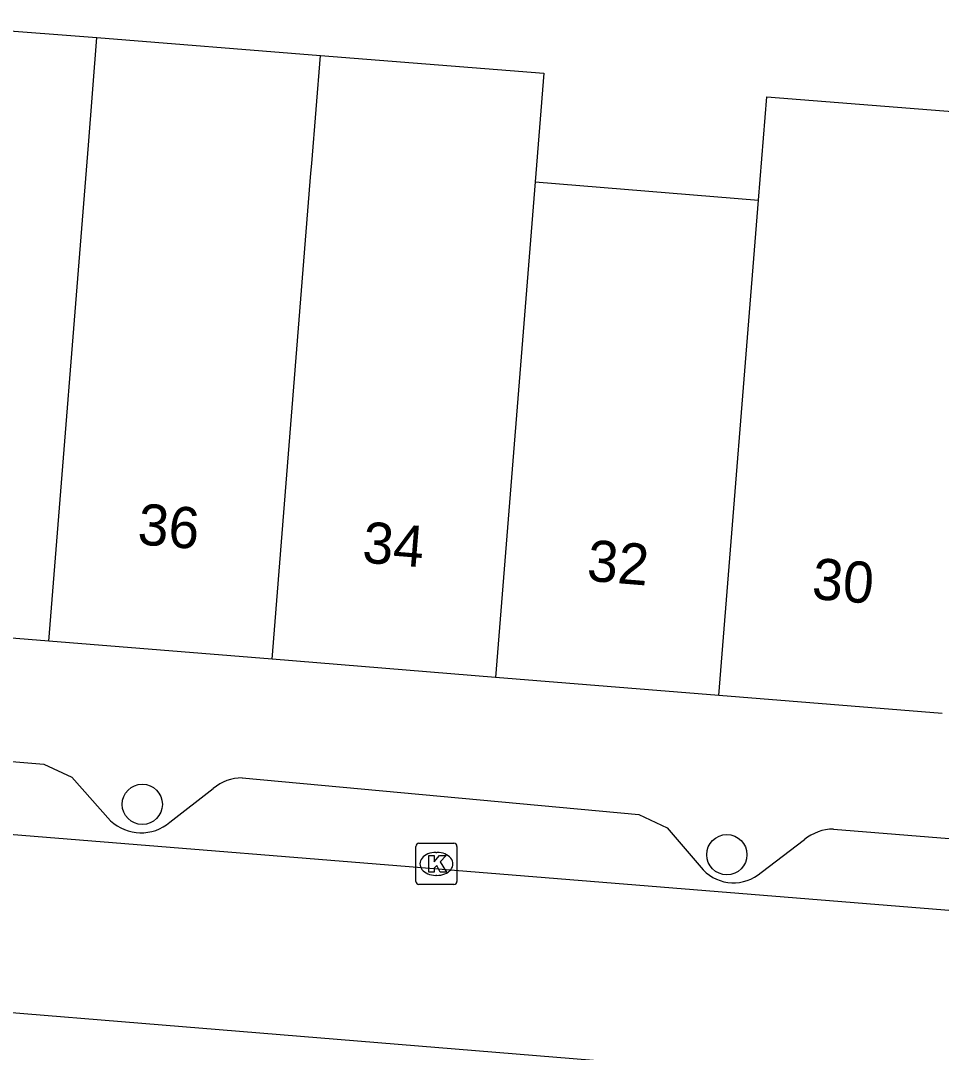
# Model space of a CAD drawing. Extents: x 159961 to 160856, y 382704 to 383353.
# Drawn here: x 160473.36 to 160495.73, y 383140.41 to 383165.49 of the extents above; entities that cross this region are included whole.
import ezdxf

# ---------------------------------------------------------------- set-up
doc = ezdxf.new("R2010")
doc.units = 0
for name, color, linetype in [('IMGEO_Boom', 7, 'Continuous'), ('IMGEO_Kolk', 7, 'Continuous'), ('IMGEO_Pand', 7, 'Continuous'), ('IMGEO_Pand_nummerreeks', 7, 'Continuous'), ('IMGEO_Rijbaan_lokaal_open', 7, 'Continuous'), ('IMGEO_Voetpad_open', 7, 'Continuous')]:
    doc.layers.add(name, color=color, linetype=linetype)

msp = doc.modelspace()

# ---------------------------------------------------------------- linework, layer by layer
at = {"layer": 'IMGEO_Boom'}
for centre in [(160476.316, 383146.443), (160490.517, 383145.219)]:
    msp.add_circle(centre, 0.489, dxfattribs=at)
at = {"layer": 'IMGEO_Kolk'}
for p, q in [((160483.035, 383145.496), (160483.887, 383145.496)), ((160482.96, 383144.57), (160482.96, 383145.422)), ((160483.448, 383145.276), (160483.473, 383145.276)), ((160483.961, 383145.422), (160483.961, 383144.57)), ((160483.471, 383144.716), (160483.446, 383144.716)), ((160483.887, 383144.496), (160483.035, 383144.496))]:
    msp.add_line(p, q, dxfattribs=at)
for points in [[(160483.035, 383145.496), (160483.887, 383145.496)], [(160482.96, 383144.57), (160482.96, 383145.422)], [(160483.961, 383145.422), (160483.961, 383144.57)], [(160483.281, 383145.196), (160483.404, 383145.196), (160483.404, 383145.045), (160483.534, 383145.196), (160483.698, 383145.196), (160483.552, 383145.045), (160483.705, 383144.796), (160483.553, 383144.796), (160483.468, 383144.96), (160483.404, 383144.893), (160483.404, 383144.796), (160483.281, 383144.796), (160483.281, 383145.196)], [(160483.887, 383144.496), (160483.035, 383144.496)]]:
    msp.add_lwpolyline(points, dxfattribs=at)
for centre, start, end in [((160483.037, 383145.42), 91.552, 178.448), ((160483.037, 383145.42), 91.552, 178.448), ((160483.885, 383145.42), 1.552, 88.448), ((160483.885, 383145.42), 1.552, 88.448), ((160483.037, 383144.572), 181.552, 268.448), ((160483.037, 383144.572), 181.552, 268.448), ((160483.885, 383144.572), 271.552, 358.448), ((160483.885, 383144.572), 271.552, 358.448)]:
    msp.add_arc(centre, 0.0765, start, end, dxfattribs=at)
for centre, major_axis, ratio, start_param, end_param in [((160483.447, 383144.996), (-0.387, 0.002), 0.722429, 4.712389, 7.853982), ((160483.472, 383144.996), (-0.39, 0.002), 0.717154, 1.570796, 4.712389)]:
    msp.add_ellipse(centre, major_axis=major_axis, ratio=ratio, start_param=start_param, end_param=end_param, dxfattribs=at)
at = {"layer": 'IMGEO_Pand'}
for points in [[(160469.592, 383162.75), (160469.605, 383162.902), (160469.818, 383165.491), (160475.216, 383165.08)], [(160474.043, 383150.409), (160475.007, 383162.461), (160475.216, 383165.08)], [(160475.216, 383165.08), (160480.643, 383164.646)], [(160479.469, 383149.969), (160480.414, 383161.782), (160480.433, 383162.017), (160480.643, 383164.646)], [(160480.643, 383164.646), (160486.072, 383164.211), (160485.861, 383161.574)], [(160491.287, 383161.13), (160491.488, 383163.641), (160496.916, 383163.207), (160496.875, 383162.699)], [(160485.861, 383161.574), (160484.897, 383149.53)], [(160485.861, 383161.574), (160491.287, 383161.13)], [(160490.325, 383149.09), (160491.287, 383161.13)], [(160474.043, 383150.409), (160468.611, 383150.848)], [(160479.469, 383149.969), (160474.043, 383150.409)], [(160484.897, 383149.53), (160479.469, 383149.969)], [(160490.325, 383149.09), (160484.897, 383149.53)], [(160495.751, 383148.651), (160490.325, 383149.09)]]:
    msp.add_lwpolyline(points, dxfattribs=at)
at = {"layer": 'IMGEO_Rijbaan_lokaal_open'}
for points in [[(160506.325, 383143.017), (160451.26, 383147.475)], [(160464.336, 383142.106), (160505.467, 383138.732)]]:
    msp.add_lwpolyline(points, dxfattribs=at)
at = {"layer": 'IMGEO_Voetpad_open'}
for points in [[(160454.18, 383149.085), (160457.63, 383148.773), (160473.923, 383147.421), (160474.607, 383147.1), (160475.547, 383146.045)], [(160478.744, 383147.088), (160488.381, 383146.193), (160489.065, 383145.872), (160489.941, 383144.852)], [(160476.986, 383146.01), (160478.041, 383146.83)], [(160493.107, 383145.843), (160507.361, 383144.687), (160509.28, 383144.526)], [(160491.354, 383144.79), (160492.404, 383145.585)]]:
    msp.add_lwpolyline(points, dxfattribs=at)
for centre, radius, start, end in [((160478.753, 383145.977), 1.111, 90.4512, 129.855), ((160476.286, 383146.822), 1.072, 226.4258, 310.7876), ((160493.116, 383144.732), 1.111, 90.4512, 129.855), ((160490.68, 383145.558), 1.022, 223.6889, 311.2862)]:
    msp.add_arc(centre, radius, start, end, dxfattribs=at)

# ---------------------------------------------------------------- texts
at = {"layer": 'IMGEO_Pand_nummerreeks'}
for s, rotation, p in [('36', 355.3705, (160476.18, 383152.764)), ('34', 355.3705, (160481.64, 383152.322)), ('32', 355.3709, (160487.097, 383151.88)), ('30', 355.3705, (160492.563, 383151.437))]:
    msp.add_text(s, height=1, rotation=rotation, dxfattribs=at).set_placement(p)

doc.saveas('drawing.dxf')
